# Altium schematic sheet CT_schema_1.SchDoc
size 796 x 599 mm
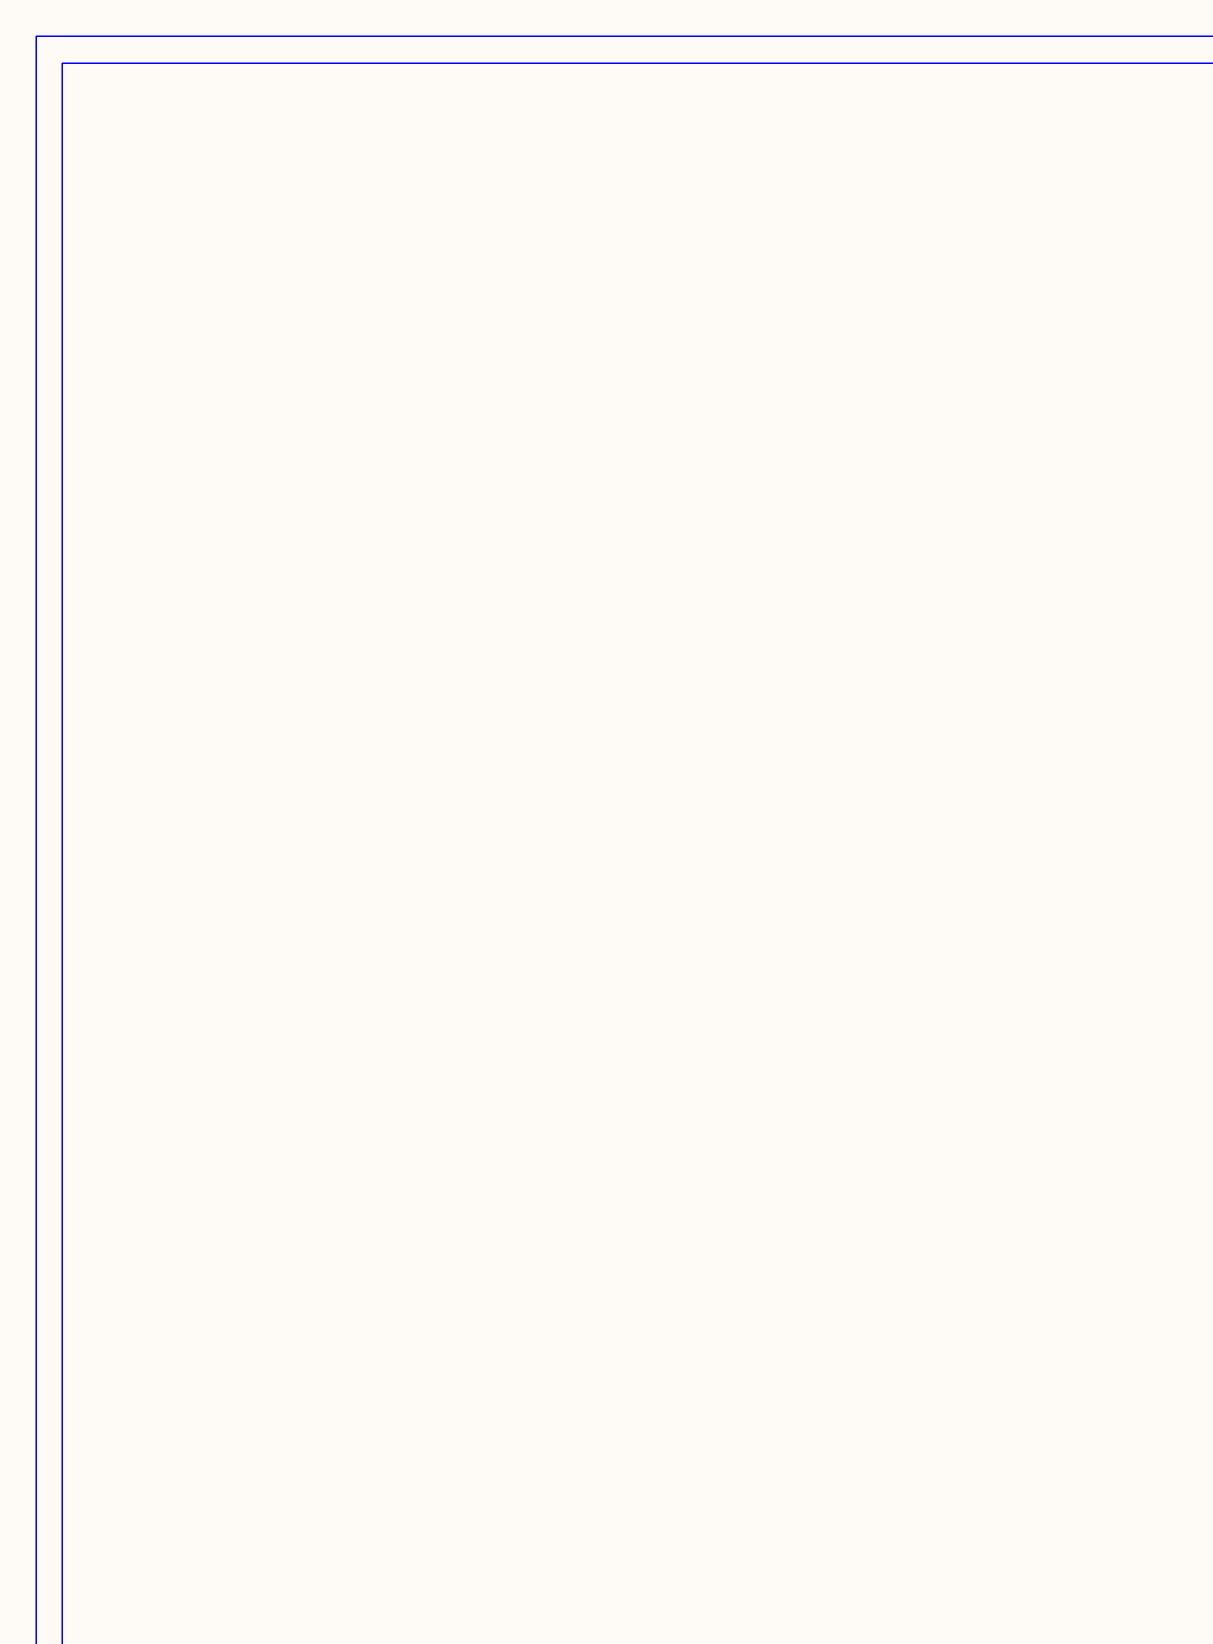
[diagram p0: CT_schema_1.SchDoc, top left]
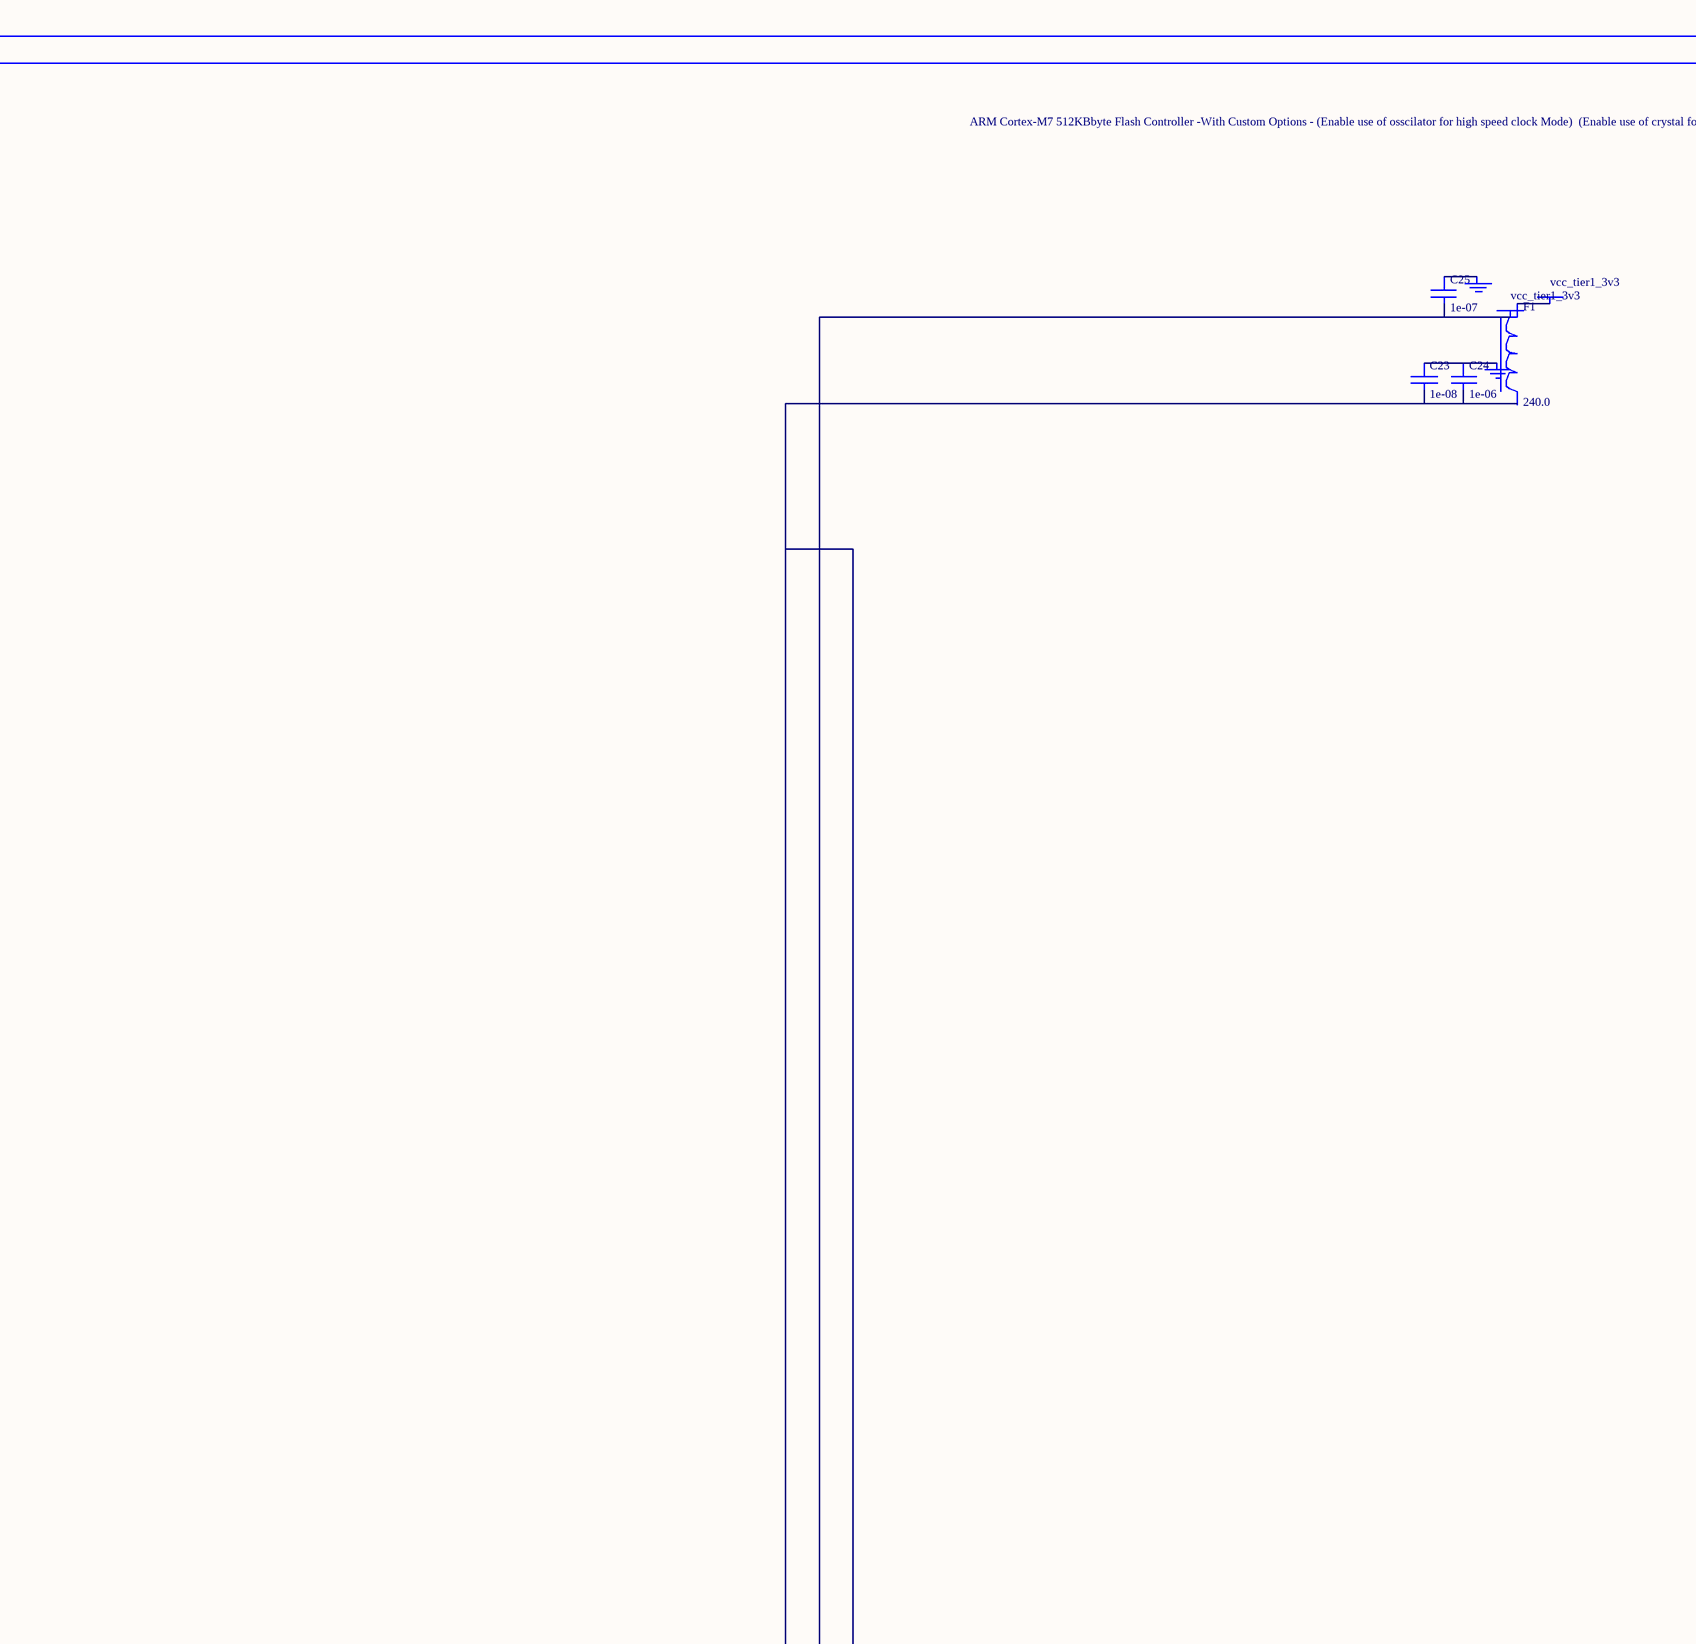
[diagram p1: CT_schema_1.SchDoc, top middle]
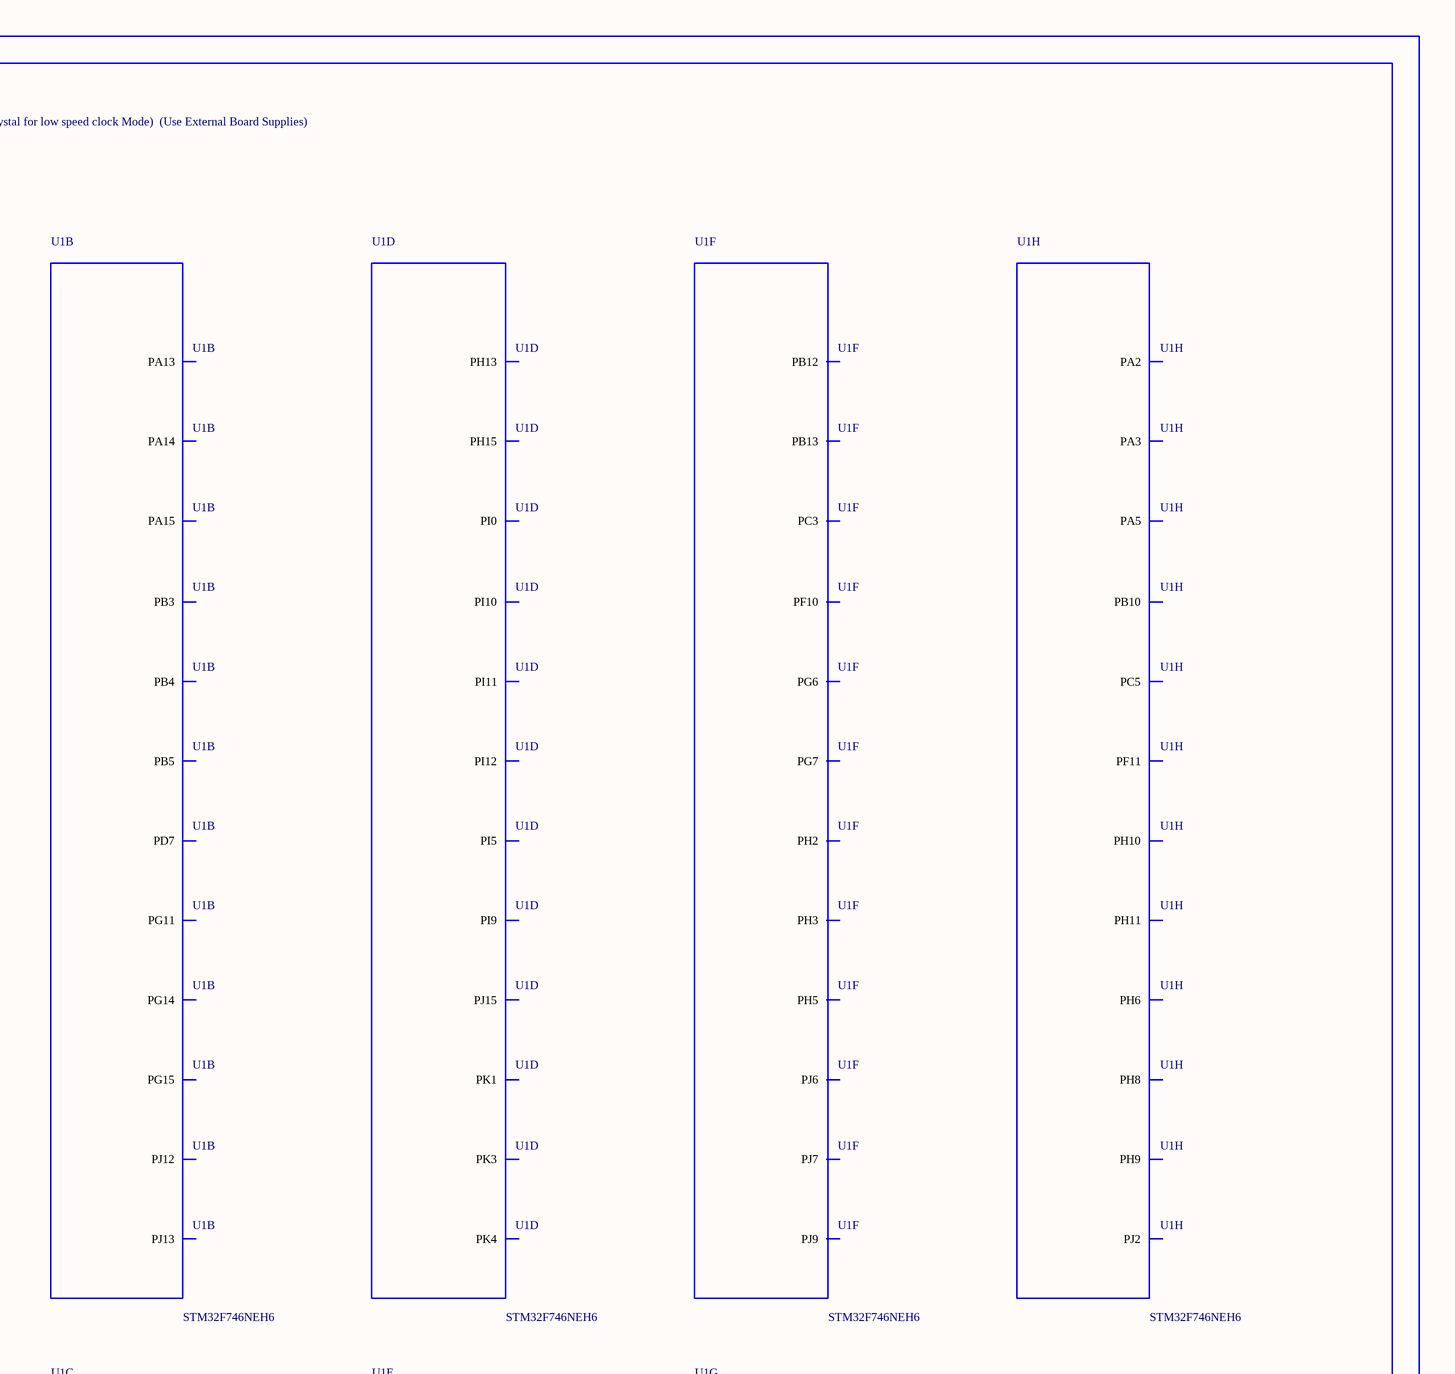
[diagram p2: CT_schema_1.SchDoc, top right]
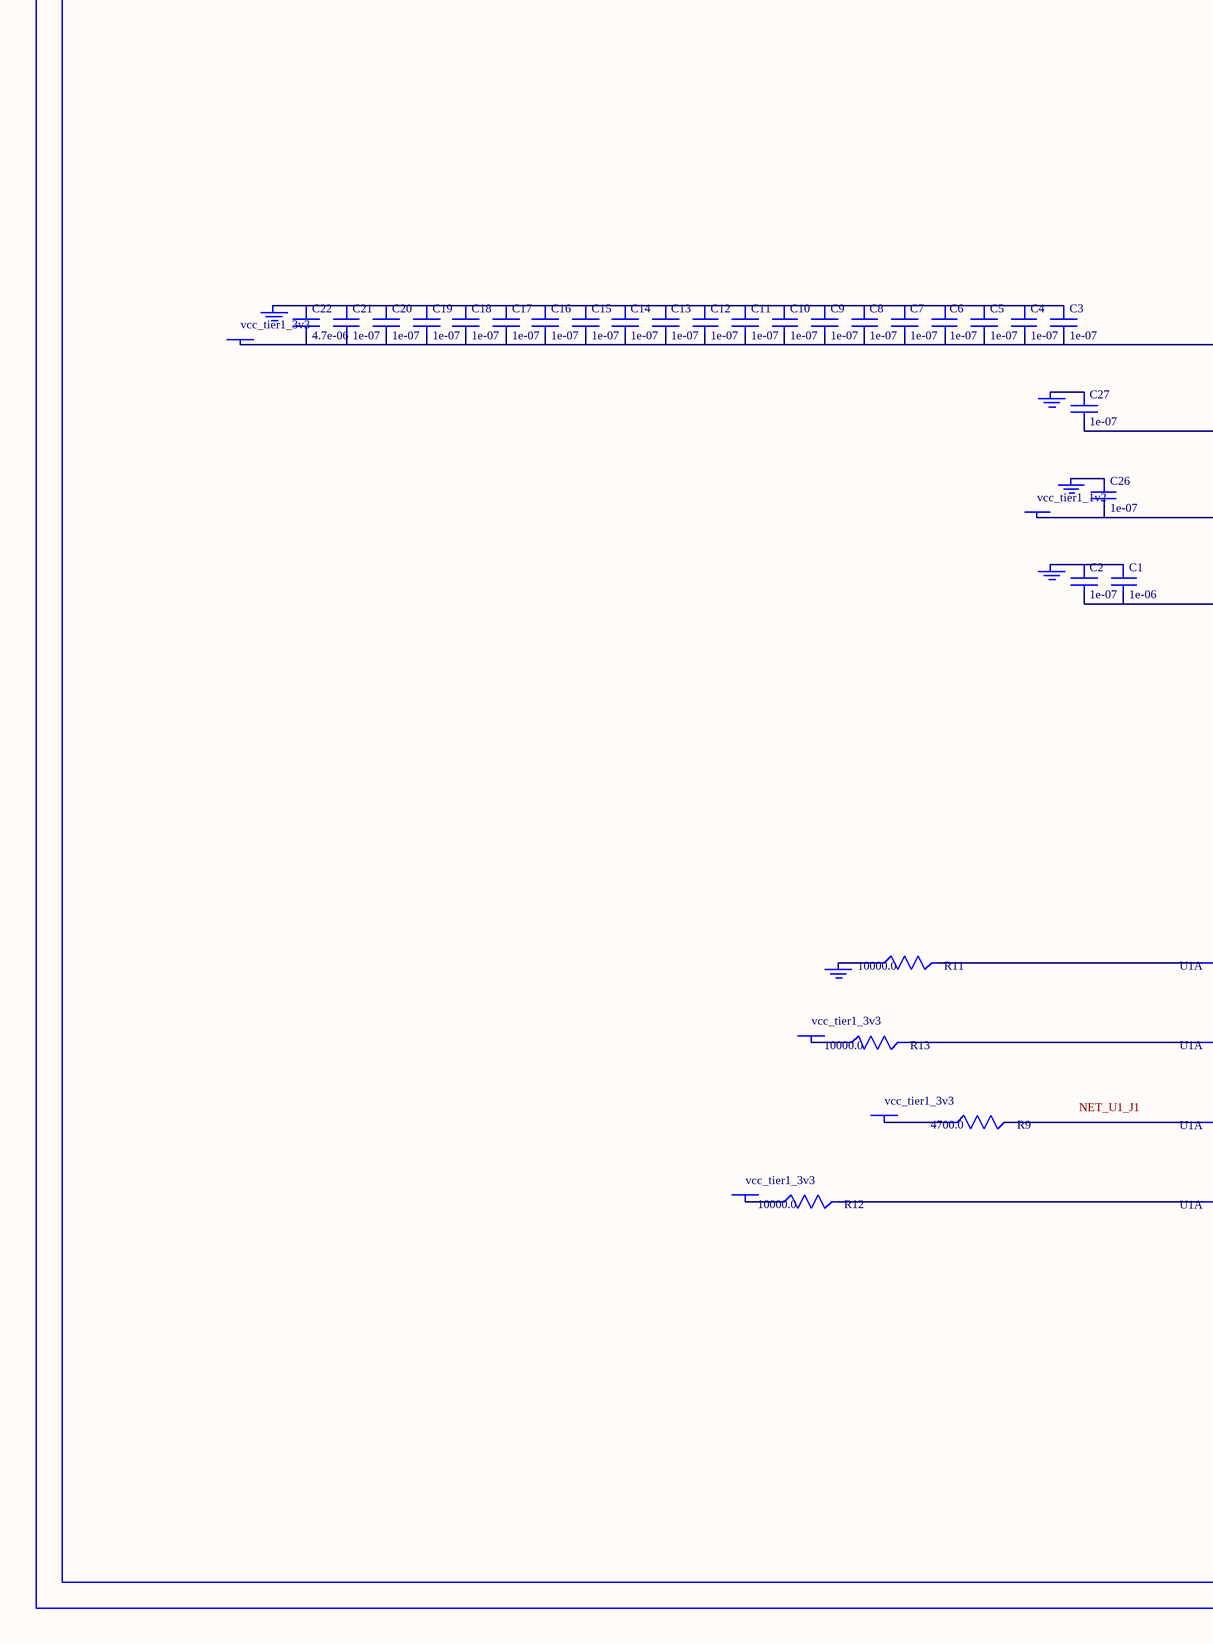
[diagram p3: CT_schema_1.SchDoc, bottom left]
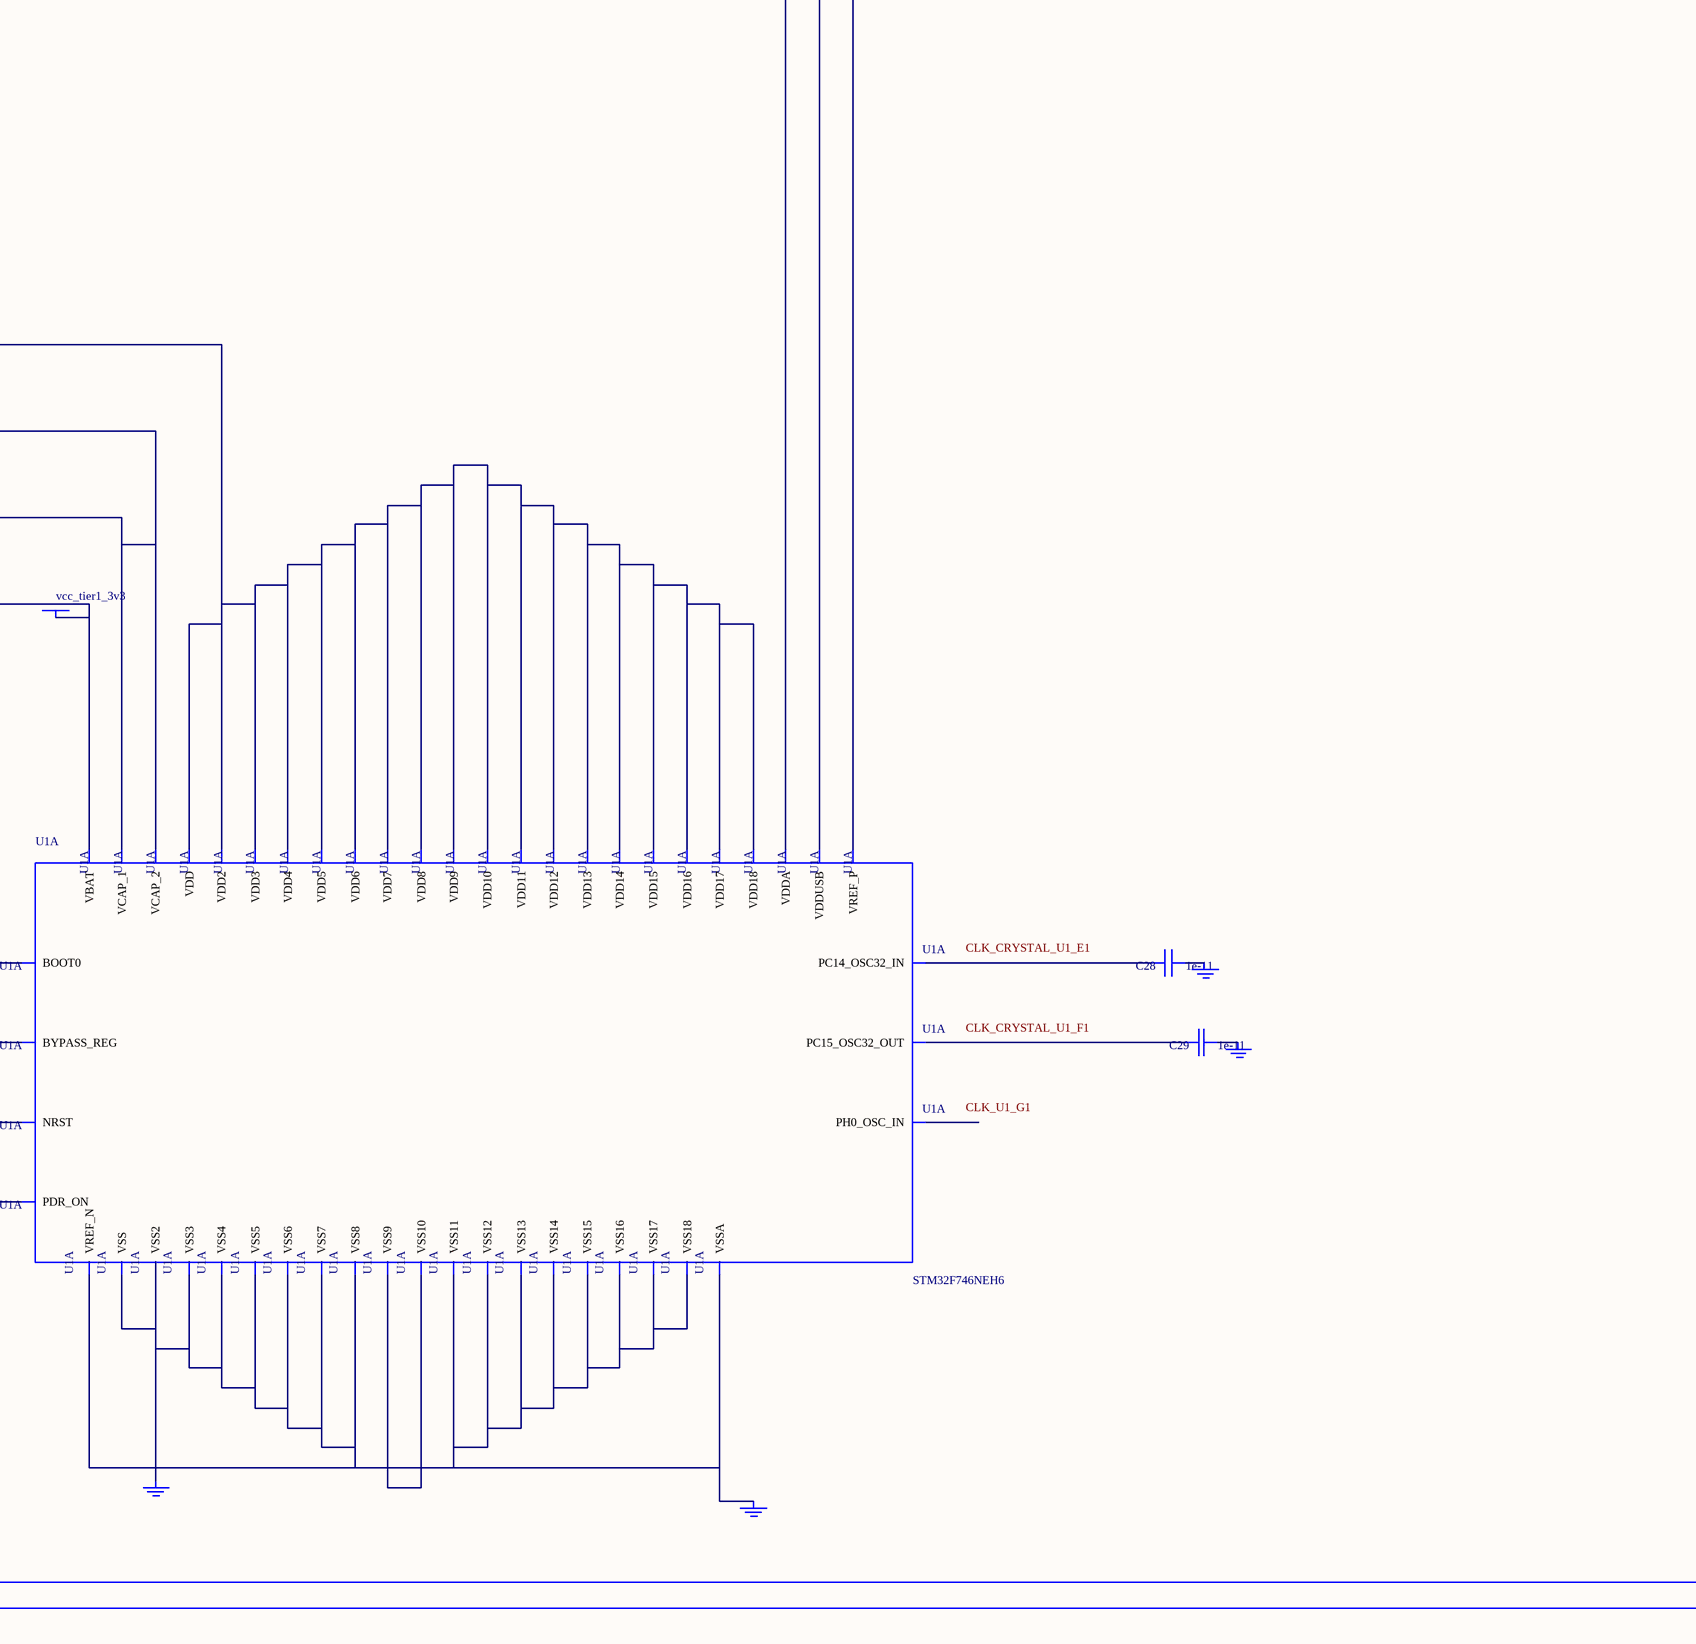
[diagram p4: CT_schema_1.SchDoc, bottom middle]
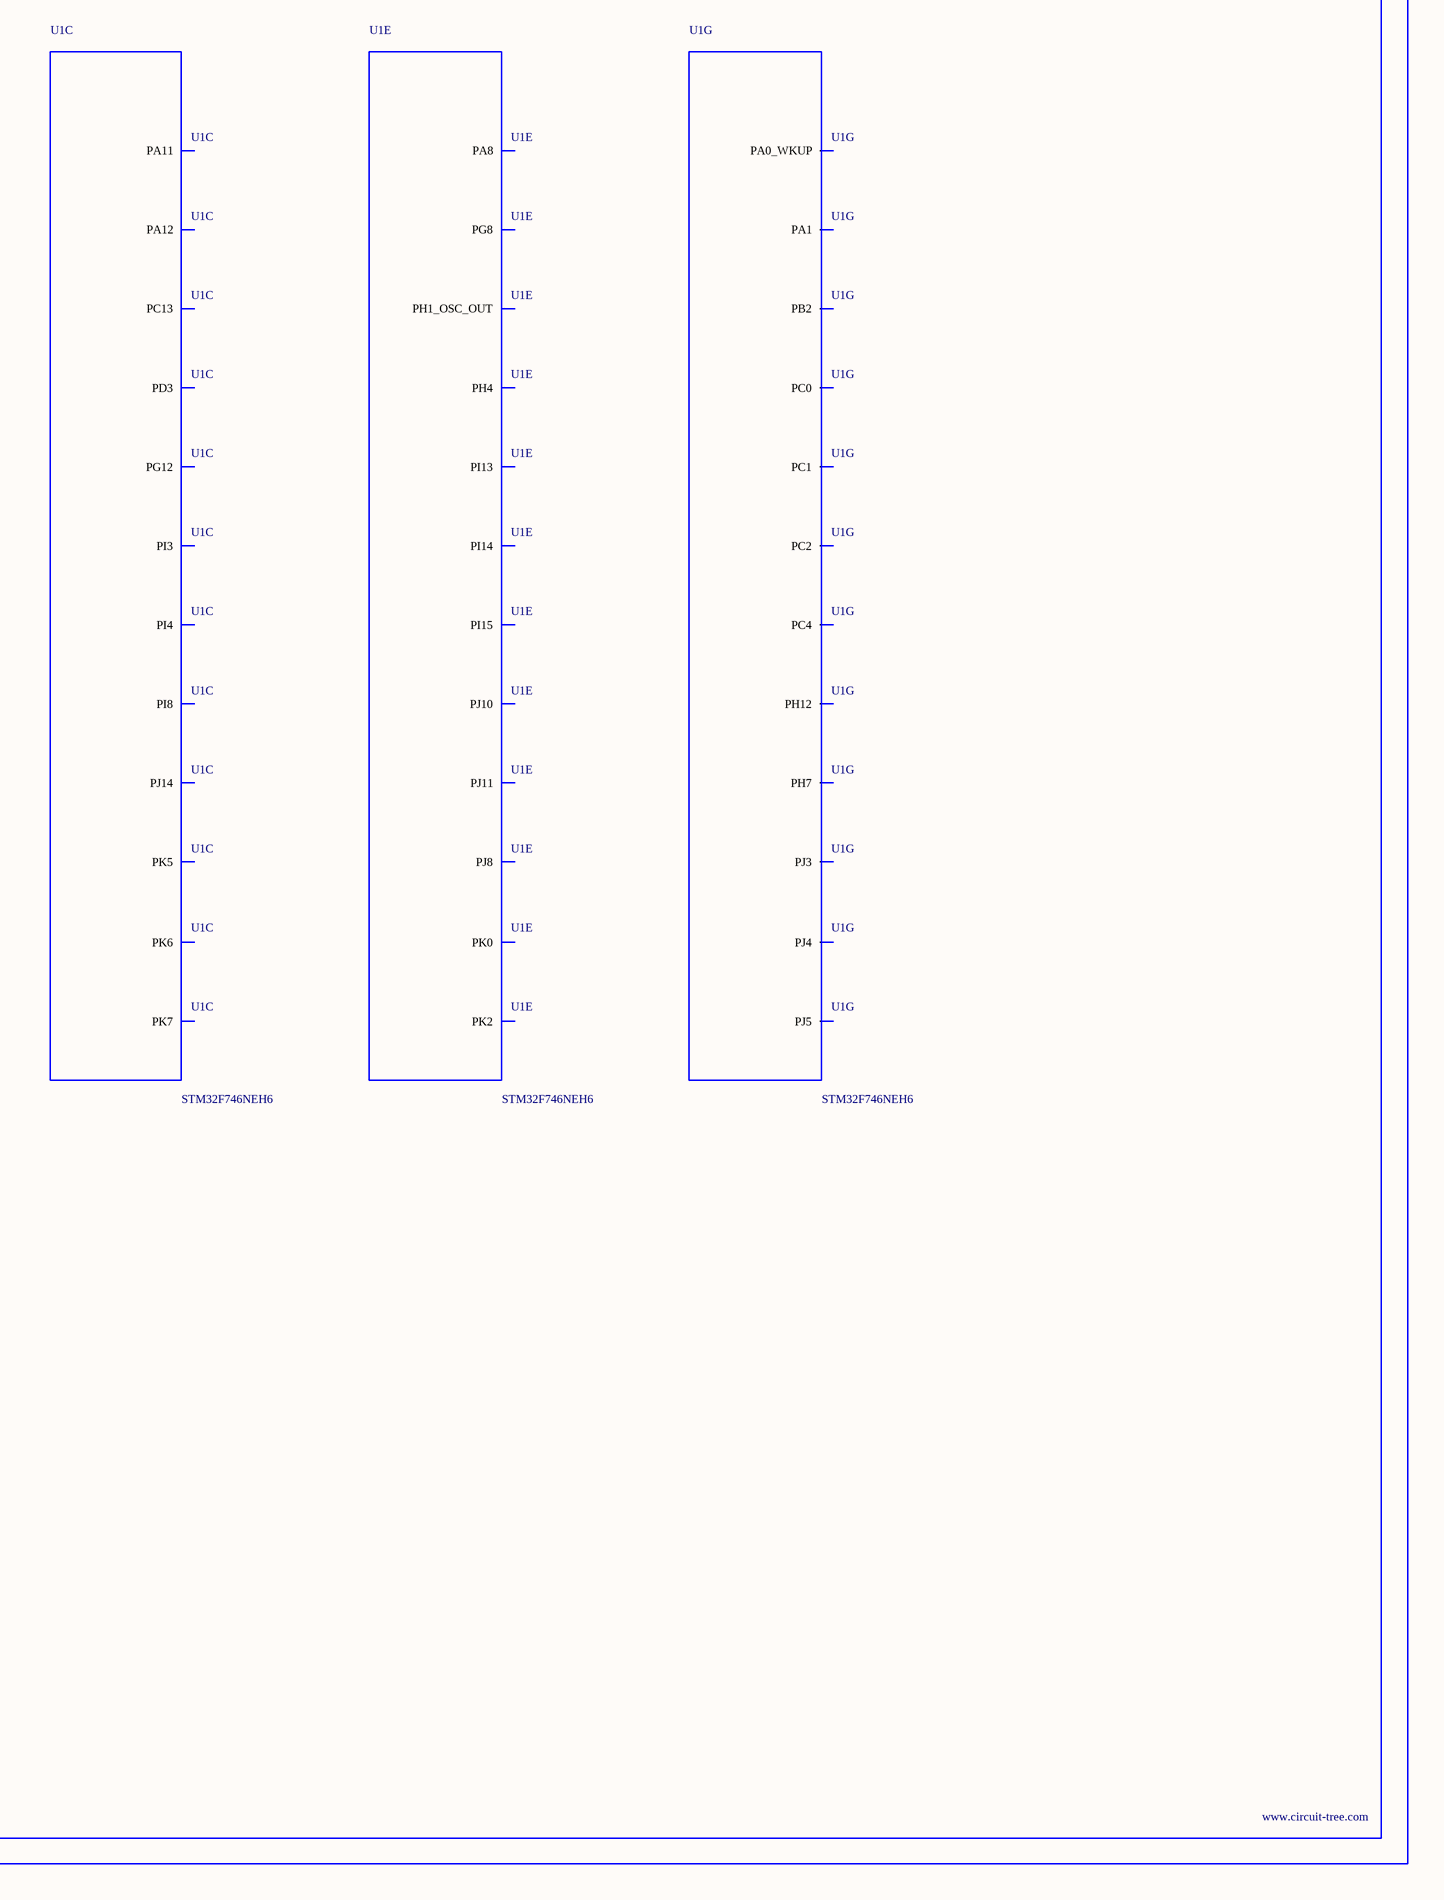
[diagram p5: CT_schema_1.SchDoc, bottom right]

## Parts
BORDER0  (no value)
C1  1e-06  [C0603]
C2  1e-07  [C0603]
C3  1e-07  [C0603]
C4  1e-07  [C0603]
C5  1e-07  [C0603]
C6  1e-07  [C0603]
C7  1e-07  [C0603]
C8  1e-07  [C0603]
C9  1e-07  [C0603]
C10  1e-07  [C0603]
C11  1e-07  [C0603]
C12  1e-07  [C0603]
C13  1e-07  [C0603]
C14  1e-07  [C0603]
C15  1e-07  [C0603]
C16  1e-07  [C0603]
C17  1e-07  [C0603]
C18  1e-07  [C0603]
C19  1e-07  [C0603]
C20  1e-07  [C0603]
C21  1e-07  [C0603]
C22  4.7e-06  [C0603]
C23  1e-08  [C0603]
C24  1e-06  [C0603]
C25  1e-07  [C0603]
C26  1e-07  [C0603]
C27  1e-07  [C0603]
C28  1e-11  [C0402]
C29  1e-11  [C0402]
F1  240.0  [L0603]
GND_INSTANCE_0_0  (no value)
GND_INSTANCE_0_1  (no value)
GND_INSTANCE_0_2  (no value)
GND_INSTANCE_0_3  (no value)
GND_INSTANCE_0_4  (no value)
GND_INSTANCE_0_5  (no value)
GND_INSTANCE_0_6  (no value)
GND_INSTANCE_0_7  (no value)
GND_INSTANCE_0_8  (no value)
GND_INSTANCE_0_9  (no value)
GND_INSTANCE_0_10  (no value)
POWER_INSTANCE_0_0  vcc_tier1_3v3
POWER_INSTANCE_0_1  vcc_tier1_3v3
POWER_INSTANCE_0_2  vcc_tier1_3v3
POWER_INSTANCE_0_3  vcc_tier1_3v3
POWER_INSTANCE_0_4  vcc_tier1_3v3
POWER_INSTANCE_0_5  vcc_tier1_3v3
POWER_INSTANCE_0_6  vcc_tier1_1v2
POWER_INSTANCE_0_7  vcc_tier1_3v3
R9  4700.0  [R0603]
R11  10000.0  [R0603]
R12  10000.0  [R0603]
R13  10000.0  [R0603]
U1  STM32F746NEH6  [TFBGA216]  (parts A,B,C,D,E,F,G,H of 14)

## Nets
NetC1_1: C1.1 C2.1 GND_INSTANCE_0_0.0(GND)
NetC1_2: C1.2 C2.2 POWER_INSTANCE_0_0.0(PWR) U1.C1(VBAT)
NetC3_1: C3.1 C4.1 C5.1 C6.1 C7.1 C8.1 C9.1 C10.1 C11.1 C12.1 C13.1 C14.1 C15.1 C16.1 C17.1 C18.1 C19.1 C20.1 C21.1 C22.1 GND_INSTANCE_0_2.0(GND)
NetC3_2: C3.2 C4.2 C5.2 C6.2 C7.2 C8.2 C9.2 C10.2 C11.2 C12.2 C13.2 C14.2 C15.2 C16.2 C17.2 C18.2 C19.2 C20.2 C21.2 C22.2 POWER_INSTANCE_0_2.0(PWR) U1.E7(VDD2) U1.E8(VDD3) U1.E9(VDD4) U1.E10(VDD) U1.F4(VDD6) U1.F5(VDD7) U1.F11(VDD5) U1.G5(VDD8) U1.H5(VDD10) U1.H11(VDD9) U1.J5(VDD12) U1.J11(VDD11) U1.K5(VDD14) U1.K11(VDD13) U1.L7(VDD16) U1.L8(VDD17) U1.L9(VDD18) U1.L10(VDD15)
NetC23_1: C23.1 C24.1 GND_INSTANCE_0_1.0(GND)
NetC23_2: C23.2 C24.2 U1.P1(VREF_P) U1.R1(VDDA)
NetC25_1: C25.1 GND_INSTANCE_0_4.0(GND)
NetC25_2: C25.2 POWER_INSTANCE_0_4.0(PWR) U1.G11(VDDUSB)
NetC26_1: C26.1 GND_INSTANCE_0_5.0(GND)
NetC26_2: C26.2 C27.2 POWER_INSTANCE_0_6.0(PWR) U1.E11(VCAP_2) U1.L11(VCAP_1)
NetC27_1: C27.1 GND_INSTANCE_0_6.0(GND)
NetC28_1: C28.1 GND_INSTANCE_0_7.0(GND)
NetC28_2: C28.2 U1.E1(PC14_OSC32_IN)
NetC29_1: C29.1 GND_INSTANCE_0_8.0(GND)
NetC29_2: C29.2 U1.F1(PC15_OSC32_OUT)
NetF1_1: F1.1 POWER_INSTANCE_0_1.0(PWR)
NetGND_INSTANCE_0_3_0: GND_INSTANCE_0_3.0(GND) R11.1
NetGND_INSTANCE_0_9_0: GND_INSTANCE_0_9.0(GND) GND_INSTANCE_0_10.0(GND) U1.F2(VSS2) U1.F6(VSS3) U1.F7(VSS4) U1.F8(VSS5) U1.F9(VSS6) U1.F10(VSS) U1.G6(VSS8) U1.G10(VSS7) U1.H6(VSS10) U1.H10(VSS9) U1.J6(VSS12) U1.J10(VSS11) U1.K6(VSS14) U1.K7(VSS15) U1.K8(VSS16) U1.K9(VSS17) U1.K10(VSS13) U1.L6(VSS18) U1.M1(VSSA) U1.N1(VREF_N)
NetPOWER_INSTANCE_0_3_0: POWER_INSTANCE_0_3.0(PWR) R12.1
NetPOWER_INSTANCE_0_5_0: POWER_INSTANCE_0_5.0(PWR) R13.1
NetPOWER_INSTANCE_0_7_0: POWER_INSTANCE_0_7.0(PWR) R9.1
NetR9_2: R9.2 U1.J1(NRST)
NetR11_2: R11.2 U1.E6(BOOT0)
NetR12_2: R12.2 U1.E5(PDR_ON)
NetR13_2: R13.2 U1.L5(BYPASS_REG)

Not connected (* = marked no-connect by the designer): F1 2; U1 A4(PG14) A8(PB5) A9(PB4) A10(PB3) A11(PD7) A13(PA15) A14(PA14) A15(PA13) B7(PG15) B8(PG11) B9(PJ13) B10(PJ12) B15(PA12) C2(PI8) C3(PI4) C4(PK7) C5(PK6) C6(PK5) C7(PG12) C9(PJ14) C11(PD3) C13(PI3) C15(PA11) D1(PC13) D3(PI5) D5(PI10) D7(PK4) D8(PK3) D10(PJ15) D13(PH15) E3(PI12) E4(PI9) E12(PH13) E14(PI0) F3(PI11) F12(PK1) F13(PK2) F15(PA8) G1(PH0_OSC_IN) G3(PI13) G4(PI15) G12(PJ11) G13(PK0) H1(PH1_OSC_OUT) H3(PI14) H4(PH4) H12(PJ8) H13(PJ10) H14(PG8) J3(PH5) J4(PH3) J12(PJ7) J13(PJ9) J14(PG7) J15(PG6) K4(PH2) K12(PJ6) K14(PB13) L1(PF10) L4(PC3) L13(PB12) M2(PC0) M3(PC1) M4(PC2) M5(PB2) M9(PJ4) M14(PJ5) M15(PH12) N2(PA1) N3(PA0_WKUP) N5(PC4) N8(PJ3) N13(PH7) N14(PH9) N15(PH11) P2(PA2) P4(PA5) P5(PC5) P7(PJ2) P8(PF11) P12(PB10) P13(PH6) P14(PH8) P15(PH10) R2(PA3)

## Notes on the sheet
- Labels drawn without touching a wire or pin: CLK_CRYSTAL_U1_E1, CLK_CRYSTAL_U1_F1, CLK_U1_G1, NET_U1_J1

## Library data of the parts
BORDER0 = BORDER_PAGE0
C1 C24 = C0603C105K3RACTU
C2-C21 C25-C27 = 06035C104K4Z2A
C22 = GRM188R6YA475KE15D
C23 = 06035C103K4Z2A
C28 C29 = C0402C100K3GACTU
F1 = Z0603C241ASMST
GND_INSTANCE_0_0-GND_INSTANCE_0_10 = GND
POWER_INSTANCE_0_0-POWER_INSTANCE_0_7 = PWR
R9 = RC0603JR-074K7L
R11-R13 = RC0603JR-0710KL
